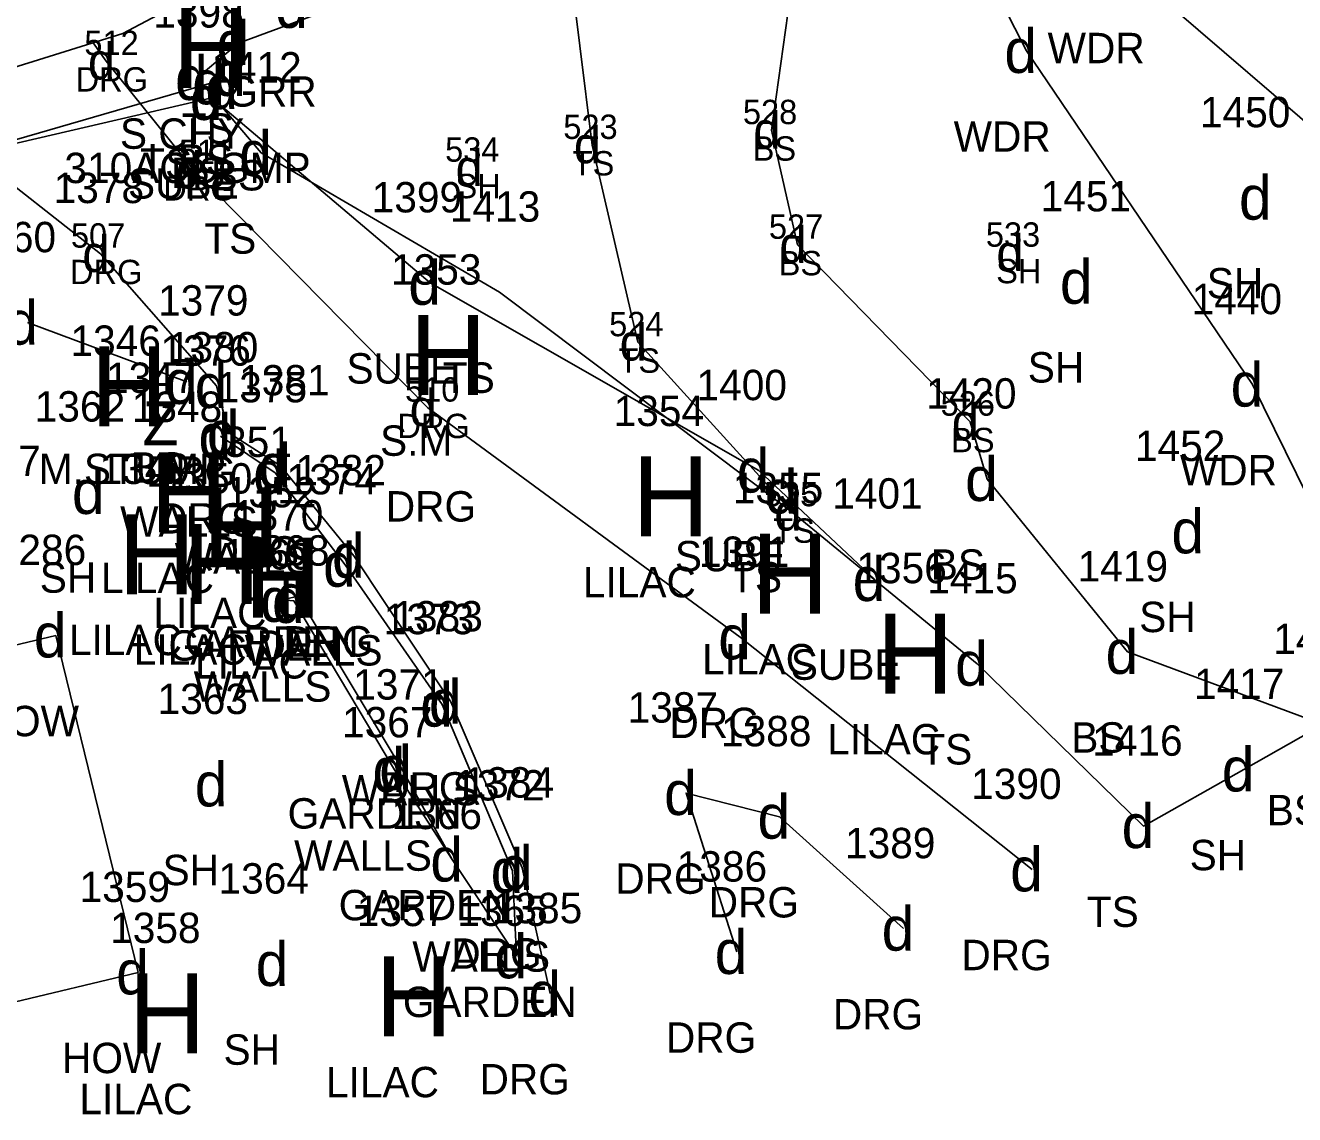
# Model space of a CAD drawing. Extents: x 461160 to 461373, y 202903 to 203086.
# Drawn here: x 461282.42 to 461314.15, y 202921.48 to 202948.72 of the extents above; entities that cross this region are included whole.
import ezdxf

# ---------------------------------------------------------------- set-up
doc = ezdxf.new("R2010")
doc.units = 0
for name, color, linetype in [('Level 11', 7, 'Continuous'), ('Level 12', 7, 'Continuous'), ('Level 13', 7, 'Continuous'), ('Level 14', 7, 'Continuous'), ('Level 15', 7, 'Continuous'), ('Level 46', 7, 'Continuous'), ('Level 47', 7, 'Continuous'), ('Level 48', 7, 'Continuous'), ('Level 49', 7, 'Continuous'), ('Level 59', 7, 'Continuous')]:
    doc.layers.add(name, color=color, linetype=linetype)

msp = doc.modelspace()

# ---------------------------------------------------------------- linework, layer by layer
at = {"layer": 'Level 11'}
for p, q in [((461289.379, 202950.925), (461284.854, 202948.511)), ((461277.244, 202946.143), (461284.854, 202948.511)), ((461292.485, 202939.158), (461286.631, 202945.099)), ((461284.301, 202943.008), (461287.202, 202939.701)), ((461300.293, 202933.416), (461292.485, 202939.158))]:
    msp.add_line(p, q, dxfattribs=at)
for points in [[(461286.631, 202945.099), (461284.44, 202947.824), (461284.118, 202948.282)], [(461278.937, 202946.67), (461281.047, 202945.559), (461284.301, 202943.008)], [(461287.202, 202939.701), (461287.507, 202938.53), (461288.795, 202937.705), (461290.635, 202935.456), (461293.058, 202931.804), (461294.838, 202927.649), (461295.544, 202924.507)], [(461307.592, 202927.613), (461300.293, 202933.416)], [(461300.204, 202925.548), (461298.939, 202929.523), (461301.274, 202928.931), (461304.378, 202926.132)]]:
    msp.add_lwpolyline(points, dxfattribs=at)
at = {"layer": 'Level 12'}
for points in [[(461294.698, 202925.44), (461294.602, 202927.576), (461292.839, 202931.734), (461290.412, 202935.231), (461288.663, 202937.531), (461287.297, 202938.45)], [(461294.698, 202925.44), (461293.094, 202927.86), (461291.817, 202930.154), (461289.242, 202934.448), (461288.837, 202934.352), (461289.135, 202934.326), (461291.647, 202930.099), (461293.094, 202927.86)]]:
    msp.add_lwpolyline(points, dxfattribs=at)
at = {"layer": 'Level 13'}
for points in [[(461269.939, 202927.688), (461269.552, 202929.221), (461276.743, 202930.893), (461276.564, 202931.887), (461283.181, 202933.463)], [(461278.681, 202923.472), (461285.239, 202925.038), (461283.181, 202933.463)]]:
    msp.add_lwpolyline(points, dxfattribs=at)
at = {"layer": 'Level 14'}
msp.add_lwpolyline([(461316.688, 202932.462), (461313.104, 202939.736), (461307.447, 202948.079), (461304.23, 202954.345), (461309.796, 202950.292), (461316.233, 202944.748), (461322.68, 202941.312), (461327.281, 202938.198)], dxfattribs=at)
at = {"layer": 'Level 15'}
msp.add_lwpolyline([(461266.383, 202941.371), (461278.58, 202944.397), (461279.146, 202945.068), (461287.08, 202946.903), (461292.543, 202942.281), (461300.755, 202937.586), (461303.654, 202934.874)], dxfattribs=at)
at = {"layer": 'Level 48'}
for p, q in [((461301.078, 202946.096), (461301.869, 202951.826)), ((461301.728, 202943.229), (461301.078, 202946.096)), ((461296.588, 202945.726), (461297.734, 202940.793)), ((461306.039, 202938.806), (461301.728, 202943.229)), ((461297.734, 202940.793), (461301.603, 202936.541))]:
    msp.add_line(p, q, dxfattribs=at)
for points in [[(461294.593, 202952.063), (461296.848, 202953.201), (461295.974, 202950.697), (461296.588, 202945.726)], [(461294.593, 202952.063), (461290.48, 202949.284), (461287.747, 202948.275), (461286.711, 202947.403), (461288.313, 202945.529), (461294.278, 202942.049), (461301.603, 202936.541), (461306.215, 202932.756), (461310.378, 202928.695), (461312.884, 202930.112), (461314.866, 202931.237), (461309.977, 202933.052), (461306.465, 202937.375), (461306.039, 202938.806)], [(461282.469, 202941.285), (461286.459, 202939.802)], [(461282.469, 202941.285), (461286.459, 202939.802)]]:
    msp.add_lwpolyline(points, dxfattribs=at)
at = {"layer": 'Level 59'}
msp.add_lwpolyline([(461279.175, 202944.985), (461287.14, 202947.294)], dxfattribs=at)

# ---------------------------------------------------------------- texts
at = {"layer": 'Level 14'}
for s, height, p in [('H', 2, (461286.096, 202947.152)), ('H', 2, (461292.024, 202939.475)), ('H', 2, (461284.048, 202938.694)), ('Z', 1.1, (461285.35, 202938.217)), ('H', 2, (461285.541, 202936.042)), ('H', 2, (461297.589, 202935.938)), ('H', 2, (461286.853, 202935.166)), ('H', 2, (461284.739, 202934.49)), ('H', 2, (461286.36, 202934.251)), ('H', 2, (461287.892, 202933.906)), ('H', 2, (461300.57, 202934.01)), ('H', 2, (461303.698, 202932.009)), ('H', 2, (461291.167, 202923.435)), ('H', 2, (461285.001, 202923.012))]:
    msp.add_text(s, height=height, dxfattribs=at).set_placement(p)
at = {"layer": 'Level 46'}
for s, height, p in [('512', 0.609, (461283.894, 202947.976)), (' WDR  ', 0.76, (461307.696, 202947.772)), ('DRG', 0.609, (461283.676, 202947.063)), (' GRR  ', 0.76, (461287.163, 202946.685)), ('528', 0.609, (461300.359, 202946.248)), (' S.CHY  ', 0.76, (461284.502, 202945.632)), (' TS  ', 0.76, (461286.045, 202945.755)), ('523', 0.609, (461295.869, 202945.878)), (' WDR  ', 0.76, (461305.347, 202945.559)), ('511', 0.609, (461286.257, 202945.251)), (' BS  ', 0.76, (461285.974, 202944.984)), ('534', 0.609, (461292.914, 202945.309)), ('BS', 0.609, (461300.604, 202945.335)), (' 310ACCGMP  ', 0.76, (461283.113, 202944.774)), (' TS  ', 0.76, (461285.009, 202944.883)), (' BS  ', 0.76, (461285.779, 202944.654)), ('TS', 0.609, (461296.104, 202944.965)), (' SUBE  ', 0.76, (461284.702, 202944.383)), (' BS  ', 0.76, (461286.777, 202944.59)), ('DRG', 0.609, (461285.867, 202944.338)), ('SH', 0.609, (461293.173, 202944.396)), ('527', 0.609, (461301.009, 202943.381)), ('533', 0.609, (461306.434, 202943.183)), ('507', 0.609, (461283.558, 202943.16)), (' TS  ', 0.76, (461286.611, 202943.009)), ('DRG', 0.609, (461283.537, 202942.247)), ('BS', 0.609, (461301.254, 202942.468)), ('SH', 0.609, (461306.693, 202942.27)), (' SH  ', 0.76, (461311.676, 202941.89)), ('524', 0.609, (461297.015, 202940.945)), ('TS', 0.609, (461297.25, 202940.032)), (' SUBE  ', 0.76, (461290.165, 202939.761)), (' SH  ', 0.76, (461307.199, 202939.787)), (' TS  ', 0.76, (461292.576, 202939.529)), ('510', 0.609, (461291.912, 202939.31)), ('526', 0.609, (461305.303, 202938.958)), (' S.M  ', 0.76, (461291.005, 202937.955)), ('DRG', 0.609, (461291.721, 202938.397)), ('BS', 0.609, (461305.565, 202938.045)), (' M.STUMP  ', 0.76, (461282.472, 202937.247)), (' BS  ', 0.76, (461284.769, 202937.282)), (' DRG  ', 0.76, (461285.15, 202937.181)), (' WDR  ', 0.76, (461311.004, 202937.216)), ('525', 0.609, (461300.884, 202936.693)), (' DRG  ', 0.76, (461291.149, 202936.311)), (' WALLS  ', 0.76, (461284.506, 202935.93)), (' DRG  ', 0.76, (461285.455, 202936.01)), ('TS', 0.609, (461301.119, 202935.78)), (' DRG  ', 0.76, (461286.743, 202935.185)), (' WALLS  ', 0.76, (461285.872, 202935.011)), (' SUBE  ', 0.76, (461298.377, 202935.066)), (' BS  ', 0.76, (461304.775, 202934.855)), (' SH  ', 0.76, (461282.497, 202934.531)), (' LILAC  ', 0.76, (461284.028, 202934.522)), (' TS  ', 0.76, (461299.758, 202934.54)), (' LILAC  ', 0.76, (461296.076, 202934.418)), (' LILAC  ', 0.76, (461285.34, 202933.646)), (' SH  ', 0.76, (461309.987, 202933.546)), (' LILAC  ', 0.76, (461283.226, 202932.97)), (' GARDEN  ', 0.76, (461286.119, 202932.928)), (' DRG  ', 0.76, (461288.583, 202932.936)), (' LILAC  ', 0.76, (461284.847, 202932.731)), (' GARDEN  ', 0.76, (461285.714, 202932.832)), (' WALLS  ', 0.76, (461287.621, 202932.711)), (' LILAC  ', 0.76, (461286.379, 202932.386)), (' LILAC  ', 0.76, (461299.057, 202932.49)), (' SUBE  ', 0.76, (461301.276, 202932.354)), (' WALLS  ', 0.76, (461286.344, 202931.806)), (' HOW  ', 0.76, (461280.994, 202930.943)), (' DRG  ', 0.76, (461298.241, 202930.896)), (' LILAC  ', 0.76, (461302.185, 202930.489)), (' BS  ', 0.76, (461308.287, 202930.532)), (' TS  ', 0.76, (461304.513, 202930.236)), (' WALLS  ', 0.76, (461290.048, 202929.214)), (' DRG  ', 0.76, (461291.006, 202929.284)), (' GARDEN  ', 0.76, (461288.694, 202928.634)), (' BS  ', 0.76, (461313.176, 202928.717)), (' WALLS  ', 0.76, (461288.856, 202927.579)), (' SH  ', 0.76, (461311.248, 202927.592)), (' SH  ', 0.76, (461285.568, 202927.218)), (' DRG  ', 0.76, (461296.887, 202927.003)), (' GARDEN  ', 0.76, (461289.971, 202926.34)), (' DRG  ', 0.76, (461299.222, 202926.411)), (' TS  ', 0.76, (461308.676, 202926.175)), (' WALLS  ', 0.76, (461291.811, 202925.056)), (' DRG  ', 0.76, (461292.786, 202925.129)), (' DRG  ', 0.76, (461305.54, 202925.093)), (' GARDEN  ', 0.76, (461291.575, 202923.92)), (' DRG  ', 0.76, (461302.326, 202923.612)), (' SH  ', 0.76, (461287.092, 202922.728)), (' DRG  ', 0.76, (461298.152, 202923.028)), (' HOW  ', 0.76, (461283.052, 202922.518)), (' LILAC  ', 0.76, (461289.654, 202921.915)), (' DRG  ', 0.76, (461293.492, 202921.987)), (' LILAC  ', 0.76, (461283.488, 202921.492))]:
    msp.add_text(s, height=height, dxfattribs=at).set_placement(p)
at = {"layer": 'Level 47'}
for height, p in [(1.1, (461288.665, 202948.655)), (1.1, (461287.197, 202947.725)), (1.1, (461306.897, 202947.529)), (0.914, (461283.983, 202947.367)), (1.1, (461286.161, 202946.853)), (1.1, (461287.114, 202946.954)), (1.1, (461286.59, 202946.744)), (1.1, (461286.919, 202946.624)), (1.1, (461286.53, 202946.353)), (0.914, (461300.621, 202945.639)), (1.1, (461287.763, 202944.979)), (0.914, (461296.131, 202945.269)), (0.914, (461286.174, 202944.642)), (0.914, (461293.176, 202944.7)), (1.1, (461312.762, 202943.86)), (0.914, (461283.844, 202942.551)), (0.914, (461301.271, 202942.772)), (0.914, (461306.696, 202942.574)), (1.1, (461291.993, 202941.731)), (1.1, (461308.285, 202941.757)), (1.1, (461281.919, 202940.735)), (0.914, (461297.277, 202940.336)), (1.1, (461285.909, 202939.252)), (1.1, (461286.652, 202939.151)), (1.1, (461312.554, 202939.186)), (0.914, (461292.028, 202938.701)), (1.1, (461286.747, 202937.9)), (1.1, (461286.957, 202937.98)), (0.914, (461305.582, 202938.349)), (1.1, (461288.113, 202936.981)), (1.1, (461288.245, 202937.155)), (1.1, (461300.205, 202937.036)), (1.1, (461305.915, 202936.825)), (1.1, (461283.583, 202936.501)), (1.1, (461300.91, 202936.51)), (0.914, (461301.146, 202936.084)), (1.1, (461311.073, 202935.516)), (1.1, (461290.085, 202934.906)), (1.1, (461289.862, 202934.681)), (1.1, (461303.104, 202934.324)), (1.1, (461288.287, 202933.802)), (1.1, (461288.585, 202933.776)), (1.1, (461288.692, 202933.898)), (1.1, (461282.631, 202932.913)), (1.1, (461299.743, 202932.866)), (1.1, (461309.427, 202932.502)), (1.1, (461305.665, 202932.206)), (1.1, (461292.508, 202931.254)), (1.1, (461292.289, 202931.184)), (1.1, (461291.097, 202929.549)), (1.1, (461291.267, 202929.604)), (1.1, (461312.334, 202929.562)), (1.1, (461286.654, 202929.188)), (1.1, (461298.389, 202928.973)), (1.1, (461300.724, 202928.381)), (1.1, (461309.828, 202928.145)), (1.1, (461292.544, 202927.31)), (1.1, (461294.288, 202927.099)), (1.1, (461294.052, 202927.026)), (1.1, (461307.042, 202927.063)), (1.1, (461303.828, 202925.582)), (1.1, (461294.148, 202924.89)), (1.1, (461299.654, 202924.998)), (1.1, (461288.178, 202924.698)), (1.1, (461284.689, 202924.488)), (1.1, (461294.994, 202923.957))]:
    msp.add_text('d', height=height, dxfattribs=at).set_placement(p)
at = {"layer": 'Level 49'}
for s, p in [(' 1398 ', (461285.336, 202948.663)), (' 1412 ', (461286.785, 202947.289)), (' 1450 ', (461311.505, 202946.17)), (' 1378 ', (461282.843, 202944.274)), (' 1399 ', (461290.796, 202944.041)), (' 1451 ', (461307.522, 202944.067)), (' 1413 ', (461292.75, 202943.809)), (' 1360 ', (461280.644, 202943.045)), (' 1353 ', (461291.28, 202942.235)), (' 1379 ', (461285.455, 202941.461)), (' 1440 ', (461311.297, 202941.496)), (' 1346 ', (461283.265, 202940.454)), (' 1376 ', (461285.514, 202940.21)), (' 1380 ', (461285.7, 202940.29)), (' 1347 ', (461284.156, 202939.527)), (' 1375 ', (461286.919, 202939.291)), (' 1381 ', (461287.482, 202939.465)), (' 1400 ', (461298.918, 202939.346)), (' 1420 ', (461304.658, 202939.135)), (' 1362 ', (461282.371, 202938.811)), (' 1348 ', (461284.797, 202938.802)), (' 1354 ', (461296.845, 202938.698)), (' 1351 ', (461286.54, 202937.926)), (' 1452 ', (461309.879, 202937.826)), (' 1287 ', (461280.261, 202937.448)), (' 1349 ', (461283.992, 202937.25)), (' 1350 ', (461285.553, 202937.011)), (' 1382 ', (461288.891, 202937.216)), (' 1374 ', (461288.668, 202936.991)), (' 1355 ', (461299.826, 202936.77)), (' 1352 ', (461287.148, 202936.666)), (' 1401 ', (461302.311, 202936.634)), (' 1370 ', (461287.328, 202936.086)), (' 1286 ', (461281.398, 202935.223)), (' 1369 ', (461287.072, 202935.112)), (' 1368 ', (461287.48, 202935.208)), (' 1391 ', (461298.98, 202935.176)), (' 1419 ', (461308.446, 202934.812)), (' 1356 ', (461302.915, 202934.769)), (' 1415 ', (461304.687, 202934.516)), (' 1383 ', (461291.314, 202933.564)), (' 1373 ', (461291.095, 202933.494)), (' 1418 ', (461313.338, 202932.997)), (' 1371 ', (461290.334, 202931.859)), (' 1417 ', (461311.356, 202931.872)), (' 1363 ', (461285.442, 202931.498)), (' 1387 ', (461297.195, 202931.283)), (' 1367 ', (461290.055, 202930.914)), (' 1388 ', (461299.53, 202930.691)), (' 1416 ', (461308.811, 202930.455)), (' 1384 ', (461293.094, 202929.409)), (' 1372 ', (461292.858, 202929.336)), (' 1390 ', (461305.785, 202929.373)), (' 1366 ', (461291.293, 202928.62)), (' 1389 ', (461302.631, 202927.892)), (' 1386 ', (461298.421, 202927.308)), (' 1364 ', (461286.966, 202927.008)), (' 1359 ', (461283.492, 202926.798)), (' 1385 ', (461293.8, 202926.267)), (' 1357 ', (461290.423, 202926.195)), (' 1365 ', (461292.936, 202926.2)), (' 1358 ', (461284.257, 202925.772))]:
    msp.add_text(s, height=0.76, dxfattribs=at).set_placement(p)

doc.saveas('drawing.dxf')
